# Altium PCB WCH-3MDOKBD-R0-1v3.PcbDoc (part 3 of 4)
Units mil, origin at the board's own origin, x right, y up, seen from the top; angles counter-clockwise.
Board outline 11710.74 x 4477.49 mil, 2 copper layers (Top Layer, Bottom Layer); 233 components, 145 nets, 545 pads, 1448 vias.
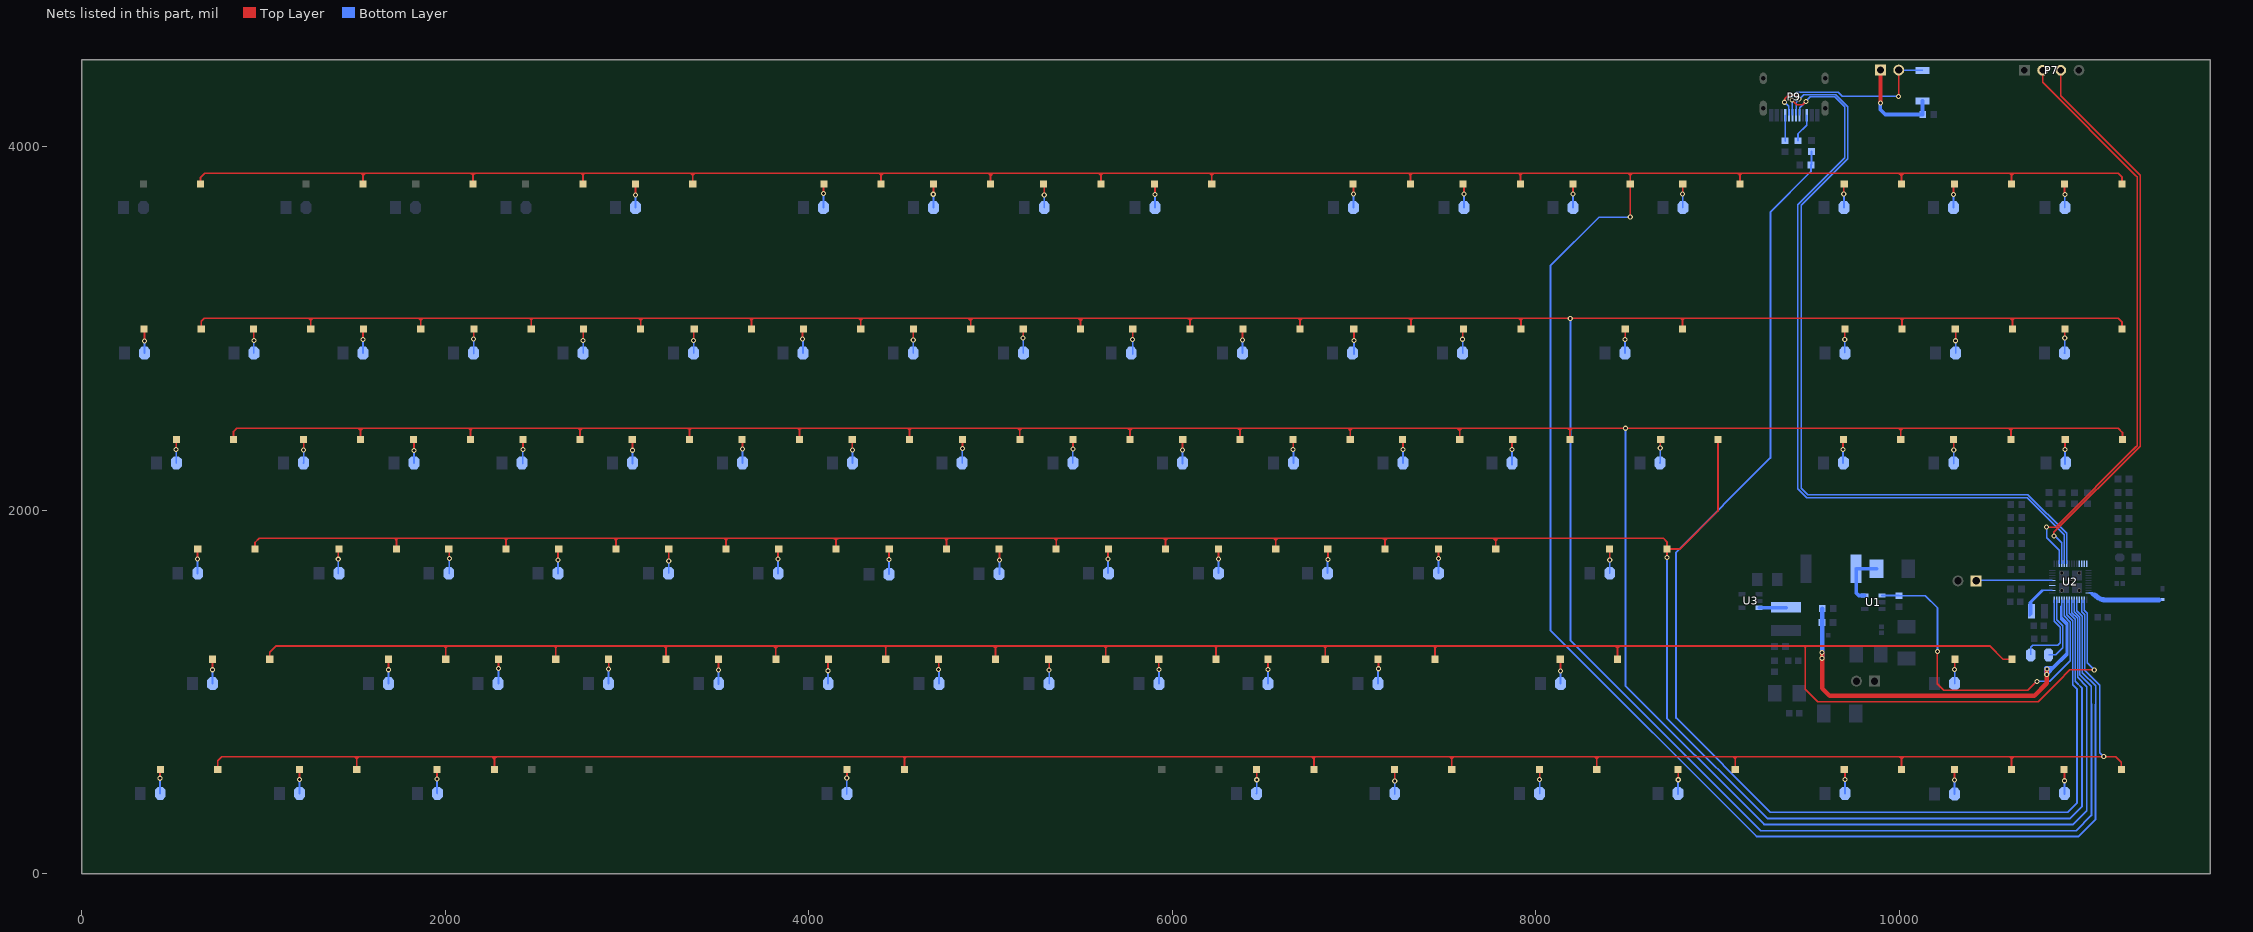
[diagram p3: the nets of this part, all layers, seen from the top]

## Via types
v1: diameter 28, hole 16, Top Layer to Bottom Layer, tented both sides, 1320 vias
v2: diameter 24, hole 12, Top Layer to Bottom Layer, tented both sides, 128 vias

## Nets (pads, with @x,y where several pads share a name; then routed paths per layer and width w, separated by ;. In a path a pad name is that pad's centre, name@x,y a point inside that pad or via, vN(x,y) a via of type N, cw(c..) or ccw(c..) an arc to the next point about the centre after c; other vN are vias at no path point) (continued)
NetD5_1: D5.1 S5.2 | length 134
  Top Layer w10: v1(3047.21,3732.37) 3047.38,3732.54 S5.2@3047.38,3793.8
  Bottom Layer w10: D5.1@3046.47,3664.15 v1@3046.47,3736.66
NetD6_1: D6.1 S6.2 | length 137.1
  Top Layer w10: v1(4081.34,3740.42) S6.2@4081.34,3798.84
  Bottom Layer w10: D6.1@4080.6,3664.02 v1@4080.6,3742.7
NetD7_1: D7.1 S7.2 | length 148
  Top Layer w10: v1(346.44,2930.45) S7.2@346.44,3005.08
  Bottom Layer w10: D7.1@346.44,2863.47 v1(346.44,2930.45) v1@346.44,2936.81
NetD8_1: D8.1 S8.2 | length 140.5
  Top Layer w10: v1(947.44,2931.58) S8.2@947.44,3003.99
  Bottom Layer w10: D8.1@947.44,2863.47 v1(947.44,2931.58)
NetD9_1: D9.1 S9.2 | length 141.4
  Top Layer w10: v1(1547.66,2938.16) S9.2@1547.66,3004.87
  Bottom Layer w10: D9.1@1547.66,2863.47 v1(1547.66,2938.16)
NetD10_1: D10.1 S10.2 | length 146
  Top Layer w10: v1(2157.01,2940.12) S10.2@2157.01,3005.49
  Bottom Layer w10: D10.1@2157.01,2859.47 v1(2157.01,2940.12)
NetD11_1: D11.1 S11.2 | length 142.9
  Top Layer w10: v1(2759.36,2933.25) S11.2@2759.36,3006.34
  Bottom Layer w10: D11.1@2759.36,2863.47 v1(2759.36,2933.25)
NetD12_1: D12.1 S12.2 | length 141.4
  Top Layer w10: v1(3367.08,2931.57) S12.2@3367.08,3004.9
  Bottom Layer w10: D12.1@3367.08,2863.47 3367.08,2869.62 v1(3367.08,2931.57)
NetD13_1: D13.1 S13.2 | length 144.2
  Top Layer w10: v1(520.39,2334.02) S13.2@520.39,2403.09
  Bottom Layer w10: v1(520.39,2334.02) 520.39,2259.88 D13.1@521.11,2259.16
NetD14_1: D14.1 S14.2 | length 141
  Top Layer w10: v1(1221.91,2329.7) S14.2@1221.91,2399.8
  Bottom Layer w10: D14.1@1221.16,2259.16 1221.91,2259.91 v1(1221.91,2329.7)
NetD15_1: D15.1 S15.2 | length 136.4
  Top Layer w10: v1(1828.18,2327.46) S15.2@1828.18,2395.54
  Bottom Layer w10: D15.1@1828.18,2259.16 v1(1828.18,2327.46)
NetD16_1: D16.1 S16.2 | length 144.5
  Top Layer w10: S16.2@2421.3,2396.47 2428.07,2389.7 v1(2428.07,2333.53)
  Bottom Layer w10: D16.1@2426.65,2256.21 2426.65,2333.53 v1(2428.07,2333.53)
NetD17_1: D17.1 S17.2 | length 132.6
  Top Layer w10: S17.2@3029.61,2388.74 3030.22,2388.14 v1(3030.22,2329.1)
  Bottom Layer w10: D17.1@3030.22,2256.38 v1(3030.22,2329.1)
NetD18_1: D18.1 S18.2 | length 136.8
  Top Layer w10: v1(3636.27,2335.52) S18.2@3636.27,2395.94
  Bottom Layer w10: D18.1@3636.27,2259.16 v1(3636.27,2335.52)
NetD19_1: D19.1 S19.2 | length 140.6
  Top Layer w10: v1(637.64,1731.27) S19.2@637.64,1791.23
  Bottom Layer w10: D19.1@637.64,1650.66 v1(637.64,1731.27)
NetD20_1: D20.1 S20.2 | length 140.2
  Top Layer w10: v1(1412.23,1729.57) S20.2@1412.23,1789.59
  Bottom Layer w10: D20.1@1412.23,1649.36 v1(1412.23,1729.57)
NetD21_1: D21.1 S21.2 | length 136.6
  Top Layer w10: S21.2@2020.09,1785.35 2022.85,1782.59 v1(2022.85,1732.52)
  Bottom Layer w10: D21.1@2022.85,1649.89 v1(2022.85,1732.52)
NetD22_1: D22.1 L1.2 U1.5 | length 297.9
  Bottom Layer w20: U1.5@9809.52,1530.18 9776.88,1530.18 9761.6,1545.46 L1.2@9761.6,1676.23 9762.43,1677.06 D22.1@9874.12,1677.06
NetD23_1: D23.1 S22.2 | length 139.2
  Top Layer w10: v1(2620.43,1725.84) S22.2@2620.43,1790.82
  Bottom Layer w10: D23.1@2620.43,1651.58 v1(2620.43,1725.84)
NetD25_1: D25.1 S23.2 | length 138.8
  Top Layer w10: v1(3230.17,1719.74) S23.2@3230.17,1791.5
  Bottom Layer w10: D25.1@3230.17,1652.68 v1(3230.17,1719.74)
NetD27_1: D27.1 S24.2 | length 141.8
  Top Layer w10: v1(3831.13,1729.93) S24.2@3831.13,1791.58
  Bottom Layer w10: D27.1@3831.13,1649.78 v1(3831.13,1729.93)
NetD28_1: D28.1 S25.2 | length 137.2
  Top Layer w10: v1(720.9,1121.62) S25.2@720.9,1182.43
  Bottom Layer w10: D28.1@720.9,1045.22 v1(720.9,1121.62)
NetD29_1: D29.1 S26.2 | length 133.9
  Top Layer w10: S26.2@1688.15,1178.83 1688.3,1178.68 v1(1688.3,1121.71)
  Bottom Layer w10: v1(1688.3,1121.71) 1688.3,1045.75 D29.1@1688.84,1045.22
NetD30_1: D30.1 S27.2 | length 134
  Top Layer w10: v1(2293.09,1129.34) 2293.09,1178.43 S27.2@2293.49,1178.83
  Bottom Layer w10: D30.1@2293.09,1045.02 v1(2293.09,1129.34)
NetD31_1: D31.1 S28.2 | length 146.8
  Top Layer w10: v1(2899.59,1125.29) S28.2@2899.59,1191.42
  Bottom Layer w10: D31.1@2898.24,1045.22 2898.24,1123.94 v1(2899.59,1125.29)
NetD32_1: D32.1 S29.2 | length 137.8
  Top Layer w10: v1(3503.65,1120.09) 3503.65,1178.34 S29.2@3504.14,1178.83
  Bottom Layer w10: D32.1@3503.65,1041.27 v1(3503.65,1120.09)
NetD33_1: D33.1 S30.2 | length 146.4
  Top Layer w10: v1(4106.44,1116.13) S30.2@4106.44,1191.23
  Bottom Layer w10: v1(4106.44,1116.13) 4106.44,1046.21 D33.1@4107.43,1045.22
NetD34_1: D34.1 S31.2 | length 132.3
  Top Layer w10: v1(430.8,524.84) S31.2@430.8,573.38
  Bottom Layer w10: D34.1@430.8,441.05 v1(430.8,524.84)
NetD35_1: D35.1 S32.2 | length 142.3
  Top Layer w10: v1(1198.31,517.48) S32.2@1198.31,583.2
  Bottom Layer w10: D35.1@1198.31,440.87 1198.31,449.18 v1(1198.31,517.48)
NetD36_1: D36.1 S33.2 | length 144.1
  Top Layer w10: v1(1955.94,519.52) S33.2@1955.94,584.5
  Bottom Layer w10: v1(1955.94,519.52) 1955.94,441.98 D36.1@1957.05,440.87
NetD37_1: D37.1 S34.2 | length 153.6
  Top Layer w10: v1@4211.04,518.17 S34.2@4211.04,573.38 S34.2@4211.04,584.2
  Bottom Layer w10: D37.1@4209.26,438.36 v1(4209.26,525.98)
NetD38_1: D38.1 S35.2 | length 132.9
  Top Layer w10: S35.2@6463.7,573.38 6464.36,572.72 v1(6464.36,516.16)
  Bottom Layer w10: D38.1@6464.02,440.87 6464.36,441.22 v1(6464.36,516.16)
NetD39_1: D39.1 S_Fn1.2 | length 141.3
  Top Layer w10: v1(7223.58,510.3) S_Fn1.2@7223.58,578.83
  Bottom Layer w10: D39.1@7223.58,437.53 D39.1@7223.58,440.87 v1(7223.58,510.3)
NetD40_1: D40.1 S36.2 | length 132.1
  Top Layer w10: v1(4685.16,3736.92) 4685.86,3737.61 S36.2@4685.86,3793.97
  Bottom Layer w10: D40.1@4686.32,3664.02 v1@4686.32,3738.79
NetD41_1: D41.1 S37.2 | length 140.5
  Top Layer w10: v1(5295.81,3733.02) S37.2@5295.81,3799.22
  Bottom Layer w10: D41.1@5295.81,3664.02 v1(5295.81,3733.02) v1@5295.81,3738.29
NetD42_1: D42.1 S38.2 | length 143.6
  Top Layer w10: v1(5905.07,3735.23) S38.2@5905.07,3803.59
  Bottom Layer w10: D42.1@5905.07,3664.02 v1(5905.07,3735.23) v1@5905.07,3739.32
NetD43_1: D43.1 S39.2 | length 139.5
  Top Layer w10: v1(6997.07,3739.18) S39.2@6997.07,3803.06
  Bottom Layer w10: D43.1@6995.94,3664.02 6995.94,3738.05 v1(6997.07,3739.18)
NetD44_1: D44.1 S40.2 | length 139.1
  Top Layer w10: v1(7604.2,3738.12) S40.2@7604.2,3803.15
  Bottom Layer w10: D44.1@7604.2,3664.02 v1(7604.2,3738.12)
NetD45_1: D45.1 S41.2 | length 136.4
  Top Layer w10: v1(8205.12,3739.5) S41.2@8205.12,3800.39
  Bottom Layer w10: v1(8205.12,3739.5) 8205.12,3664.13 D45.1@8205.22,3664.02
NetD46_1: D46.1 S42.2 | length 139.5
  Top Layer w10: v1(8807.11,3739.5) 8807.58,3739.98 S42.2@8807.58,3793.8 S42.2@8807.58,3801.76
  Bottom Layer w10: D46.1@8808.27,3664.02 v1@8808.27,3741.09
NetD47_1: D47.1 S43.2 | length 140.6
  Top Layer w10: v1(3966,2941.18) S43.2@3966,3003.17
  Bottom Layer w10: v1(3966,2941.18) 3968.09,2939.09 D47.1@3968.09,2863.47
NetD48_1: D48.1 S44.2 | length 141.1
  Top Layer w10: v1(4574.85,2936.23) S44.2@4574.85,3004.54
  Bottom Layer w10: D48.1@4574.85,2863.47 v1(4574.85,2936.23)
NetD49_1: D49.1 S45.2 | length 144.7
  Top Layer w10: v1(5179.6,2945.87) 5180.45,2946.72 S45.2@5180.45,2994.96 S45.2@5180.45,3007.45
  Bottom Layer w10: v1(5179.6,2945.87) 5180.47,2945 D49.1@5180.47,2863.47
NetD50_1: D50.1 S46.2 | length 137
  Top Layer w10: v1(5782.1,2937.09) S46.2@5782.1,2996.19
  Bottom Layer w10: D50.1@5782.1,2859.23 v1(5782.1,2937.09)
NetD51_1: D51.1 S47.2 | length 133.4
  Top Layer w10: v1(6386.92,2936.4) S47.2@6386.92,2996.88
  Bottom Layer w10: D51.1@6386.92,2863.47 v1(6386.92,2936.4)
NetD52_1: D52.1 S48.2 | length 150.3
  Top Layer w10: S48.2@6990.5,3003.78 6998.88,2995.4 v1(6998.88,2932.86)
  Bottom Layer w10: D52.1@6998.88,2856.99 v1(6998.88,2932.86)
NetD53_1: D53.1 S49.2 | length 138.5
  Top Layer w10: v1(7597.41,2939.64) S49.2@7597.41,3001.94
  Bottom Layer w10: D53.1@7597.3,2863.47 7597.41,2863.58 v1(7597.41,2939.64)
NetD54_1: D54.1 S50.2 | length 129.8
  Top Layer w10: S50.2@4239.53,2388.74 4239.53,2330.43 v1(4240.01,2329.95)
  Bottom Layer w10: D54.1@4239.96,2259.16 4240.01,2259.21 v1(4240.01,2329.95)
NetD55_1: D55.1 S51.2 | length 132.7
  Top Layer w10: v1(4845.53,2338.81) 4846.37,2339.65 S51.2@4846.37,2388.74
  Bottom Layer w10: D55.1@4844.14,2259.16 v1@4844.14,2341.61
NetD56_1: D56.1 S52.2 | length 132.1
  Top Layer w10: S52.2@5453.23,2388.74 5454.29,2387.68 v1(5454.29,2335.45)
  Bottom Layer w10: D56.1@5452.8,2259.16 v1@5452.8,2337.58
NetD57_1: D57.1 S53.2 | length 135.7
  Top Layer w10: v1(6055.6,2331.35) S53.2@6055.6,2389.95
  Bottom Layer w10: D57.1@6055.6,2254.23 D57.1@6055.6,2259.16 v1(6055.6,2331.35)
NetD58_1: D58.1 S54.2 | length 130.5
  Top Layer w10: S54.2@6664.28,2388.74 6664.94,2388.08 v1(6664.94,2332.01)
  Bottom Layer w10: v1(6664.94,2332.01) 6666.44,2330.51 D58.1@6666.44,2259.16
NetD59_1: D59.1 S55.2 | length 136.4
  Top Layer w10: v1(7269,2331.93) S55.2@7269,2395.49
  Bottom Layer w10: v1(7269,2331.93) 7269,2259.3 D59.1@7269.14,2259.16
NetD60_1: D60.1 S56.2 | length 146.5
  Top Layer w10: S56.2@7869.08,2390.27 v1(7869.08,2333.53) v1@7873.05,2337.49
  Bottom Layer w10: D60.1@7869.08,2249.4 D60.1@7869.08,2259.16 v1(7869.08,2333.53)
NetD61_1: D61.1 S57.2 | length 138.9
  Top Layer w10: v1(4442.36,1726.86) 4442.36,1784.96 S57.2@4442.76,1785.35
  Bottom Layer w10: D61.1@4442.3,1646.61 4442.3,1726.8 v1(4442.36,1726.86)
NetD62_1: D62.1 S58.2 | length 138.7
  Top Layer w10: S58.2@5046.27,1785.35 5048.62,1782.99 v1(5048.62,1725.98)
  Bottom Layer w10: D62.1@5048.62,1647.58 v1(5048.62,1725.98)
NetD63_1: D63.1 S59.2 | length 136.4
  Top Layer w10: v1(5646.28,1731) S59.2@5646.28,1789.39
  Bottom Layer w10: D63.1@5646.28,1653.01 v1(5646.28,1731)
NetD64_1: D64.1 S60.2 | length 133.9
  Top Layer w10: S60.2@6253.89,1785.35 6254.37,1784.87 v1(6254.37,1730.62)
  Bottom Layer w10: D64.1@6253.38,1652.04 6254.37,1653.03 v1(6254.37,1730.62)
NetD65_1: D65.1 S61.2 | length 141.2
  Top Layer w10: S61.2@6855.58,1785.35 6856.19,1784.74 v1(6856.19,1728.46)
  Bottom Layer w10: D65.1@6854.15,1651.91 v1@6854.15,1735.99
NetD66_1: D66.1 S62.2 | length 134.1
  Top Layer w10: S62.2@7464,1785.35 7464.51,1784.84 v1(7464.51,1732.79)
  Bottom Layer w10: D66.1@7463.53,1651.91 7464.51,1652.89 v1(7464.51,1732.79)
NetD67_1: D67.1 S63.2 | length 136.5
  Top Layer w10: v1(8684.1,2341.25) S63.2@8684.1,2394.85
  Bottom Layer w10: D67.1@8682.18,2259.16 8684.1,2261.08 v1(8684.1,2341.25)
NetD68_1: D68.1 S64.2 | length 149.4
  Top Layer w10: v1(4714.9,1122.33) S64.2@4714.9,1193.32
  Bottom Layer w10: D68.1@4717.14,1045.22 v1@4717.14,1123.66
NetD69_1: D69.1 S65.2 | length 133.6
  Top Layer w10: v1(5322.73,1120.41) S65.2@5322.73,1178.83
  Bottom Layer w10: D69.1@5322.73,1045.22 v1(5322.73,1120.41)
NetD70_1: D70.1 S66.2 | length 134.1
  Top Layer w10: S66.2@5925.44,1178.83 5925.44,1124.13 v1(5926.55,1123.02)
  Bottom Layer w10: D70.1@5926.55,1045.22 v1(5926.55,1123.02)
NetD71_1: D71.1 S67.2 | length 133.9
  Top Layer w10: v1(6526.43,1122.05) S67.2@6526.44,1178.83
  Bottom Layer w10: D71.1@6525.65,1045.22 6526.43,1046 v1(6526.43,1122.05)
NetD72_1: D72.1 S68.2 | length 145.1
  Top Layer w10: v1(7133.51,1126.77) S68.2@7133.51,1187.91
  Bottom Layer w10: D72.1@7131.13,1045.22 v1@7131.13,1129.15
NetD73_1: D73.1 S69.2 | length 142.6
  Top Layer w10: v1(8136.22,1113.6) S69.2@8136.22,1187.79
  Bottom Layer w10: D73.1@8136.22,1045.22 v1(8136.22,1113.6)
NetD74_1: D74.1 S71.2 | length 143.2
  Top Layer w10: v1(8020.91,518.8) S71.2@8020.91,584.11
  Bottom Layer w10: D74.1@8020.91,440.87 v1(8020.91,518.8)
NetD75_1: D75.1 S72.2 | length 144.5
  Top Layer w10: v1(8783.06,516.6) S72.2@8783.06,580.01
  Bottom Layer w10: D75.1@8781.21,437.72 D75.1@8781.21,440.87 v1@8781.21,518.79
NetD76_1: D76.1 S73.2 | length 141.6
  Top Layer w10: v1@9693.64,3735.52 v1(9693.64,3738.1) S73.2@9693.64,3802.03
  Bottom Layer w10: D76.1@9694.83,3664.02 v1@9694.83,3739.15
NetD77_1: D77.1 S74.2 | length 143
  Top Layer w10: v1(10297.44,3736.7) S74.2@10297.44,3802.98
  Bottom Layer w10: D77.1@10297.44,3664.02 v1(10297.44,3736.7) v1@10297.44,3740.8
NetD78_1: D78.1 S75.2 | length 130.2
  Top Layer w10: S75.2@10908.61,3793.8 10908.61,3737.64 v1(10909.68,3736.57)
  Bottom Layer w10: D78.1@10909.68,3664.02 v1(10909.68,3736.57)
NetD79_1: D79.1 S76.2 | length 142.5
  Top Layer w10: v1(8490.15,2938.78) 8490.46,2938.78 8491.69,2940.01 S76.2@8491.69,2994.96 S76.2@8491.69,3005.15
  Bottom Layer w10: D79.1@8490.15,2863.47 v1(8490.15,2938.78)
NetD80_1: D80.1 S77.2 | length 134.6
  Top Layer w10: v1(9699.13,2938.04) S77.2@9699.13,2999.35
  Bottom Layer w10: D80.1@9699.13,2864.77 v1(9699.13,2938.04)
NetD81_1: D81.1 S78.2 | length 139.1
  Top Layer w10: v1(10309.39,2931.52) S78.2@10309.39,3002.6
  Bottom Layer w10: D81.1@10309.39,2863.47 v1(10309.39,2931.52)
NetD82_1: D82.1 S79.2 | length 132
  Top Layer w10: v1(10909.21,2945.36) 10909.21,2994.21 S79.2@10909.97,2994.96
  Bottom Layer w10: D82.1@10908.74,2863.47 10909.21,2863.94 v1(10909.21,2945.36)
NetD83_1: D83.1 S80.2 | length 137.3
  Top Layer w10: v1(9688.8,2332.41) S80.2@9688.8,2395.19
  Bottom Layer w10: D83.1@9688.8,2257.89 v1(9688.8,2332.41)
NetD84_1: D84.1 S81.2 | length 131.5
  Top Layer w10: v1(10298.64,2329.83) S81.2@10298.64,2386.67
  Bottom Layer w10: D84.1@10298.64,2255.15 D84.1@10298.64,2259.16 v1(10298.64,2329.83)
NetD85_1: D85.1 S82.2 | length 138.7
  Top Layer w10: v1(10911.34,2332.49) S82.2@10911.34,2392.87
  Bottom Layer w10: D85.1@10911.34,2254.14 v1(10911.34,2332.49)
NetD86_1: D86.1 S83.2 | length 133.7
  Top Layer w10: S83.2@8405.85,1785.35 8406.18,1785.02 v1(8406.18,1726.29)
  Bottom Layer w10: v1(8406.18,1726.29) 8406.18,1652.29 D86.1@8406.56,1651.91
NetD87_1: D87.1 S84.2 | length 136.5
  Top Layer w10: v1(10303.89,1122.05) S84.2@10303.89,1181.77
  Bottom Layer w10: D87.1@10303.89,1045.22 v1(10303.89,1122.05)
NetD88_1: D88.1 S85.2 | length 143.9
  Top Layer w10: v1(9700.87,518.17) S85.2@9700.87,584.79
  Bottom Layer w10: D88.1@9700.87,440.87 v1(9700.87,518.17)
NetD89_1: D89.1 S86.2 | length 147.9
  Top Layer w10: v1(10303.66,514.46) S86.2@10303.66,585.44
  Bottom Layer w10: D89.1@10303.66,437.55 v1(10303.66,514.46)
NetD90_1: D90.1 S87.2 | length 148
  Top Layer w10: v1(10907.66,511.07) S87.2@10907.66,581.35
  Bottom Layer w10: D90.1@10908.26,437.41 D90.1@10908.26,441.09 v1@10908.26,515.16
NetE1_1: E1.1 U2.34 | length 564.8
  Bottom Layer w7: 11075.28,1527.52 11070.76,1532.04 ccw(c11042.5,1503.78) U2.34@11042.5,1543.75 ; 11077.67,1516.72 11056.4,1537.99 ccw(c11042.5,1524.09) U2.34@11042.5,1543.75 ; 11083.07,1526.21 11081.81,1527.47 ccw(c11042.5,1488.16) U2.34@11042.5,1543.75 ; 11083.9,1530.76 ccw(c11052.55,1499.41) U2.34@11052.55,1543.75 ; 11091.68,1532.51 ccw(c11064.53,1505.36) 11064.53,1543.75 U2.34@11052.55,1543.75 ; U2.34@11042.5,1543.75 U2.34@11052.55,1543.75
  Bottom Layer w28.1: 11083.07,1526.21 ccw(c11131.36,1574.5) 11131.36,1506.2 11426.79,1506.2
NetL2_1: L2.1 U2.2 | length 645.3
  Bottom Layer w7: 10794.37,1557.49 10791.14,1557.49 ; U2.2@10841.57,1557.49 10791.14,1557.49 ; L2.1@10714.85,1426.41 L2.1@10714.85,1439.54 ; L2.1@10714.85,1426.41 10714.85,1416.98 L2.1@10722.52,1424.64 ; L2.1@10714.85,1426.41 L2.1@10722.52,1434.08 ; L2.1@10714.85,1439.54 10720.31,1434.08 L2.1@10722.52,1434.08 ; L2.1@10714.85,1439.54 L2.1@10714.85,1454.87 ; L2.1@10714.85,1439.54 L2.1@10722.52,1447.21 ; L2.1@10714.85,1454.87 L2.1@10722.52,1462.54 ; L2.1@10714.85,1454.87 L2.1@10714.85,1469.13 ; L2.1@10714.85,1454.87 L2.1@10722.52,1447.21 ; L2.1@10714.85,1469.13 L2.1@10714.85,1477.97 ; L2.1@10714.85,1469.13 L2.1@10722.52,1469.13 ; L2.1@10714.85,1469.13 10721.44,1462.54 L2.1@10722.52,1462.54 ; L2.1@10714.85,1477.97 10719.29,1477.97 L2.1@10722.52,1481.2 ; L2.1@10714.85,1477.97 L2.1@10722.52,1470.3 ; L2.1@10714.85,1477.97 10714.85,1488.87 ; 10714.85,1488.87 L2.1@10722.52,1481.2 ; 10714.85,1488.87 10722.52,1488.87 ; 10714.85,1488.87 10783.47,1557.49 10791.14,1557.49 ; L2.1@10722.52,1424.64 L2.1@10722.52,1434.08 ; L2.1@10722.52,1424.64 10728.64,1430.77 L2.1@10728.64,1445.57 ; L2.1@10722.52,1434.08 L2.1@10722.52,1447.21 ; L2.1@10722.52,1447.21 L2.1@10722.52,1462.54 ; L2.1@10722.52,1447.21 L2.1@10726.4,1443.33 ; L2.1@10722.52,1462.54 L2.1@10722.52,1469.13 ; L2.1@10722.52,1462.54 L2.1@10726.4,1466.42 ; L2.1@10722.52,1469.13 L2.1@10722.52,1470.3 ; L2.1@10722.52,1469.13 L2.1@10723.68,1469.13 ; L2.1@10722.52,1470.3 L2.1@10722.52,1481.2 ; L2.1@10722.52,1470.3 L2.1@10723.68,1469.13 ; L2.1@10722.52,1481.2 10722.52,1488.87 ; L2.1@10722.52,1481.2 10726.4,1477.32 L2.1@10726.4,1466.42 ; 10722.52,1488.87 10728.64,1494.99 ; L2.1@10723.68,1469.13 L2.1@10726.4,1466.42 ; L2.1@10726.4,1443.33 L2.1@10726.4,1466.42 ; L2.1@10726.4,1443.33 L2.1@10728.64,1445.57 ; L2.1@10728.64,1445.57 10728.64,1494.99 ; 10728.64,1494.99 10791.14,1557.49
NetL4_1: L4.1 U3.3 | length 148.2
  Bottom Layer w20: U3.3@9228.06,1462.52 L4.1@9376.23,1462.52
NetP6_1: P6.1 R300.1 S70.1 | length 540.4
  Top Layer w20: v1@9896.11,4240.06 P6.1@9896.11,4420.24
  Bottom Layer w20: v1@9894.17,4241.92 9894.17,4203.59 9922.1,4175.66 R300.1@10128.51,4175.66 10127.09,4177.09 S70.1@10127.09,4251.02
  other v1: 9894.77,4240.06
NetP9_A5: P9.A5 R10.1 | length 142.6
  Bottom Layer w10: R10.1@9372.01,4029.54 P9.A5@9372.01,4172.15
NetP9_B5: P9.B5 R11.1 | length 159.7
  Bottom Layer w10: R11.1@9442.13,4032.34 9442.13,4068.95 9490.12,4116.94 P9.B5@9490.12,4172.15
PA0: S1.1 S2.1 S3.1 S4.1 S5.1 S6.1 S36.1 S37.1 S38.1 S39.1 S40.1 S41.1 S42.1 S73.1 S74.1 S75.1 U2.39 | length 19418.2
  Top Layer w10: S1.1@654.86,3793.8 654.86,3829.59 677.54,3852.28 1539.27,3852.28 ; S2.1@1548.73,3793.8 1548.73,3841.66 ; S3.1@2153.27,3793.8 2153.27,3841.02 ; S4.1@2757.8,3793.8 2757.8,3843.06 ; S5.1@3362.34,3793.8 3362.34,3840.86 ; S6.1@4398.26,3793.97 4398.26,3841.44 ; S36.1@5000.82,3793.97 5000.82,3839.61 ; S37.1@5607.27,3794.25 5607.27,3840.64 ; S38.1@6216.74,3794.24 6216.74,3841.77 ; S39.1@7309.83,3793.8 7309.83,3841.63 ; S40.1@7914.98,3793.8 7914.98,3841.77 ; v1@8519.58,3610.39 S41.1@8519.58,3793.88 8519.58,3841.76 ; S42.1@9122.54,3793.8 9122.54,3841.12 ; S73.1@10011.03,3793.8 10011.03,3839.1 ; S74.1@10617.3,3793.8 10617.3,3841.41 ; S75.1@11223.57,3793.8 11223.57,3832.75 11204.04,3852.28 10628.16,3852.28 ; 1539.27,3852.28 1550.27,3852.28 ; 1539.27,3852.28 1539.27,3851.12 1548.73,3841.66 ; 1548.73,3841.66 1559.35,3852.28 ; 1548.73,3841.66 1548.73,3850.74 1550.27,3852.28 ; 1550.27,3852.28 1559.35,3852.28 ; 1559.35,3852.28 2142.01,3852.28 ; 2142.01,3852.28 2154.24,3852.28 ; 2142.01,3852.28 2153.27,3841.02 ; 2153.27,3841.02 2164.52,3852.28 ; 2153.27,3841.02 2153.27,3851.31 2154.24,3852.28 ; 2154.24,3852.28 2164.52,3852.28 ; 2164.52,3852.28 2748.58,3852.28 ; 2748.58,3852.28 2758.87,3852.28 ; 2748.58,3852.28 2757.8,3843.06 ; 2757.8,3843.06 2767.02,3852.28 ; 2757.8,3843.06 2757.8,3851.21 2758.87,3852.28 ; 2758.87,3852.28 2767.02,3852.28 ; 2767.02,3852.28 3351.11,3852.28 ; 3351.11,3852.28 3360.58,3852.28 ; 3351.11,3852.28 3351.11,3852.08 3362.34,3840.86 ; 3360.58,3852.28 3373.76,3852.28 ; 3360.58,3852.28 3362.34,3850.52 3362.34,3840.86 ; 3362.34,3840.86 3373.76,3852.28 ; 3373.76,3852.28 4387.42,3852.28 ; 4387.42,3852.28 4397.66,3852.28 ; 4387.42,3852.28 4398.26,3841.44 ; 4397.66,3852.28 4409.1,3852.28 ; 4397.66,3852.28 4398.26,3851.67 4398.26,3841.44 ; 4398.26,3841.44 4409.1,3852.28 ; 4409.1,3852.28 4989.28,3852.28 ; 4989.28,3852.28 5003.72,3852.28 ; 4989.28,3852.28 4989.28,3851.15 5000.82,3839.61 ; 5000.82,3839.61 5013.48,3852.28 ; 5000.82,3839.61 5000.82,3849.37 5003.72,3852.28 ; 5003.72,3852.28 5013.48,3852.28 ; 5013.48,3852.28 5595.63,3852.28 ; 5595.63,3852.28 5605.54,3852.28 ; 5595.63,3852.28 5607.27,3840.64 ; 5605.54,3852.28 5617.82,3852.28 ; 5605.54,3852.28 5607.27,3850.55 5607.27,3841.72 ; 5607.27,3840.64 5607.27,3841.72 ; 5607.27,3841.72 5617.82,3852.28 ; 5617.82,3852.28 6206.23,3852.28 ; 6206.23,3852.28 6219.21,3852.28 ; 6206.23,3852.28 6216.74,3841.77 ; 6216.74,3841.77 6227.25,3852.28 ; 6216.74,3841.77 6216.74,3849.81 6219.21,3852.28 ; 6219.21,3852.28 6227.25,3852.28 ; 6227.25,3852.28 7299.19,3852.28 ; 7299.19,3852.28 7308.57,3852.28 ; 7299.19,3852.28 7309.83,3841.63 ; 7308.57,3852.28 7320.48,3852.28 ; 7308.57,3852.28 7309.83,3851.02 7309.83,3841.63 ; 7309.83,3841.63 7320.48,3852.28 ; 7320.48,3852.28 7904.48,3852.28 ; 7904.48,3852.28 7914.06,3852.28 ; 7904.48,3852.28 7914.98,3841.77 ; 7914.06,3852.28 7925.48,3852.28 ; 7914.06,3852.28 7914.98,3851.36 7914.98,3841.77 ; 7914.98,3841.77 7925.48,3852.28 ; 7925.48,3852.28 8509.06,3852.28 ; 8509.06,3852.28 8521.05,3852.28 ; 8509.06,3852.28 8519.58,3841.76 ; 8519.58,3841.76 8530.09,3852.28 ; 8519.58,3841.76 8519.58,3850.8 8521.05,3852.28 ; 8521.05,3852.28 8530.09,3852.28 ; 8530.09,3852.28 9112.41,3852.28 ; 9112.41,3852.28 9123.14,3852.28 ; 9112.41,3852.28 9112.41,3851.25 9122.54,3841.12 ; 9122.54,3841.12 9133.7,3852.28 ; 9122.54,3841.12 9122.54,3851.68 9123.14,3852.28 ; 9123.14,3852.28 9133.7,3852.28 ; 9133.7,3852.28 10000.77,3852.28 ; 10000.77,3852.28 10012.2,3852.28 ; 10000.77,3852.28 10000.77,3849.35 10011.03,3839.1 ; 10011.03,3839.1 10011.03,3839.54 ; 10011.03,3839.54 10011.03,3851.11 10012.2,3852.28 ; 10011.03,3839.54 10023.77,3852.28 ; 10012.2,3852.28 10023.77,3852.28 ; 10023.77,3852.28 10606.44,3852.28 ; 10606.44,3852.28 10615.06,3852.28 ; 10606.44,3852.28 10617.3,3841.41 ; 10615.06,3852.28 10628.16,3852.28 ; 10615.06,3852.28 10617.3,3850.04 10617.3,3841.41 ; 10617.3,3841.41 10628.16,3852.28
  Bottom Layer w7: U2.39@10975.43,1506.72 10975.43,1445.44 11005.99,1414.88 11005.99,1105.57 11079.24,1032.32 11079.24,929.84
  Bottom Layer w10: v1@8519.58,3610.37 8347.13,3610.37 8079.63,3342.86 8079.63,1339.01 9213.58,205.05 10986.29,205.05 11079.24,297.99 11079.24,929.84
  other v1: 8519,3611.99
PA1: S7.1 S8.1 S9.1 S10.1 S11.1 S12.1 S43.1 S44.1 S45.1 S46.1 S47.1 S48.1 S49.1 S76.1 S77.1 S78.1 S79.1 U2.40 | length 18367.1
  Top Layer w10: S7.1@658.49,2994.96 658.49,3037.98 675.4,3054.89 1248.97,3054.89 ; S8.1@1260.41,2994.96 1260.41,3043.45 ; S9.1@1866.19,2994.96 1866.19,3044.35 ; S10.1@2473.99,2994.96 2473.99,3045.8 ; S11.1@3075.53,2994.96 3075.53,3043.76 ; S12.1@3685.01,2994.96 3685.01,3044.18 ; S43.1@4286.55,2994.96 4286.55,3044.31 ; S44.1@4890.96,2994.96 4890.96,3041.8 ; S45.1@5495.41,2994.96 5495.41,3042.24 ; S46.1@6097.77,2994.96 6097.77,3043.29 ; S47.1@6703.15,2994.96 6703.15,3043.66 ; S48.1@7312.97,2994.96 7312.97,3043.68 ; S49.1@7917.42,2994.96 7917.42,3044.05 ; S76.1@8806.65,2994.96 8806.65,3043.76 ; S77.1@10014.84,2994.96 10014.84,3043.77 ; S78.1@10621.68,2994.96 10621.68,3043.67 ; S79.1@11224.93,2994.96 11224.93,3033.21 11203.25,3054.89 10632.9,3054.89 ; 1248.97,3054.89 1261.07,3054.89 ; 1248.97,3054.89 1260.41,3043.45 ; 1260.41,3043.45 1271.86,3054.89 ; 1260.41,3043.45 1260.41,3054.23 1261.07,3054.89 ; 1261.07,3054.89 1271.86,3054.89 ; 1271.86,3054.89 1855.65,3054.89 ; 1855.65,3054.89 1866.09,3054.89 ; 1855.65,3054.89 1866.19,3044.35 ; 1866.09,3054.89 1876.74,3054.89 ; 1866.09,3054.89 1866.19,3054.79 1866.19,3044.35 ; 1866.19,3044.35 1876.74,3054.89 ; 1876.74,3054.89 2464.89,3054.89 ; 2464.89,3054.89 2472.86,3054.89 ; 2464.89,3054.89 2473.99,3045.8 ; 2472.86,3054.89 2483.08,3054.89 ; 2472.86,3054.89 2473.99,3053.77 2473.99,3045.8 ; 2473.99,3045.8 2483.08,3054.89 ; 2483.08,3054.89 3064.4,3054.89 ; 3064.4,3054.89 3074.7,3054.89 ; 3064.4,3054.89 3075.53,3043.76 ; 3074.7,3054.89 3086.66,3054.89 ; 3074.7,3054.89 3075.53,3054.07 3075.53,3043.76 ; 3075.53,3043.76 3086.66,3054.89 ; 3086.66,3054.89 3674.29,3054.89 ; 3674.29,3054.89 3685.13,3054.89 ; 3674.29,3054.89 3685.01,3044.18 ; 3685.01,3044.18 3695.72,3054.89 ; 3685.01,3044.18 3685.01,3054.77 3685.13,3054.89 ; 3685.13,3054.89 3695.72,3054.89 ; 3695.72,3054.89 4275.97,3054.89 ; 4275.97,3054.89 4287.94,3054.89 ; 4275.97,3054.89 4286.55,3044.31 ; 4286.55,3044.31 4297.14,3054.89 ; 4286.55,3044.31 4286.55,3053.51 4287.94,3054.89 ; 4287.94,3054.89 4297.14,3054.89 ; 4297.14,3054.89 4877.87,3054.89 ; 4877.87,3054.89 4888.77,3054.89 ; 4877.87,3054.89 4890.96,3041.8 ; 4888.77,3054.89 4902.18,3054.89 ; 4888.77,3054.89 4890.96,3052.7 4890.96,3043.68 ; 4890.96,3041.8 4890.96,3043.68 ; 4890.96,3043.68 4902.18,3054.89 ; 4902.18,3054.89 5482.76,3054.89 ; 5482.76,3054.89 5493.4,3054.89 ; 5482.76,3054.89 5495.41,3042.24 ; 5493.4,3054.89 5508.06,3054.89 ; 5493.4,3054.89 5495.41,3052.88 5495.41,3042.24 ; 5495.41,3042.24 5508.06,3054.89 ; 5508.06,3054.89 6086.17,3054.89 ; 6086.17,3054.89 6098.42,3054.89 ; 6086.17,3054.89 6097.77,3043.29 ; 6097.77,3043.29 6109.38,3054.89 ; 6097.77,3043.29 6097.77,3054.24 6098.42,3054.89 ; 6098.42,3054.89 6109.38,3054.89 ; 6109.38,3054.89 6691.92,3054.89 ; 6691.92,3054.89 6702.66,3054.89 ; 6691.92,3054.89 6703.15,3043.66 ; 6702.66,3054.89 6714.38,3054.89 ; 6702.66,3054.89 6703.15,3054.4 6703.15,3043.66 ; 6703.15,3043.66 6714.38,3054.89 ; 6714.38,3054.89 7301.75,3054.89 ; 7301.75,3054.89 7314.46,3054.89 ; 7301.75,3054.89 7312.97,3043.68 ; 7312.97,3043.68 7324.18,3054.89 ; 7312.97,3043.68 7312.97,3053.4 7314.46,3054.89 ; 7314.46,3054.89 7324.18,3054.89 ; 7324.18,3054.89 7906.57,3054.89 ; 7906.57,3054.89 7915.55,3054.89 ; 7906.57,3054.89 7917.42,3044.05 ; 7915.55,3054.89 7928.27,3054.89 ; 7915.55,3054.89 7917.42,3053.02 7917.42,3044.05 ; 7917.42,3044.05 7928.27,3054.89 ; 7928.27,3054.89 8795.51,3054.89 ; 8795.51,3054.89 8808.68,3054.89 ; 8795.51,3054.89 8806.65,3043.76 ; 8806.65,3043.76 8806.65,3044.01 ; 8806.65,3044.01 8806.65,3052.86 8808.68,3054.89 ; 8806.65,3044.01 8817.53,3054.89 ; 8808.68,3054.89 8817.53,3054.89 ; 8817.53,3054.89 10004.66,3054.89 ; 10004.66,3054.89 10013.43,3054.89 ; 10004.66,3054.89 10004.66,3053.94 10014.84,3043.77 ; 10013.43,3054.89 10023.83,3054.89 ; 10013.43,3054.89 10014.84,3053.49 10014.84,3045.9 ; 10014.84,3043.77 10014.84,3045.9 ; 10014.84,3045.9 10023.83,3054.89 ; 10023.83,3054.89 10610.45,3054.89 ; 10610.45,3054.89 10619.31,3054.89 ; 10610.45,3054.89 10621.68,3043.67 ; 10619.31,3054.89 10632.9,3054.89 ; 10619.31,3054.89 10621.68,3052.52 10621.68,3043.67 ; 10621.68,3043.67 10632.9,3054.89
  Bottom Layer w7: U2.40@10961.65,1506.72 10961.65,1440.84 10992.99,1409.5 10992.99,1093.81 11055.73,1031.07 11055.73,933.26
  Bottom Layer w10: v1@8189.85,3053.03 8189.85,1284.46 9238.03,236.28 10971.82,236.28 11055.73,320.19 11055.73,933.26
  other v1: 8189.08,3053.03
PA2: S13.1 S14.1 S15.1 S16.1 S17.1 S18.1 S50.1 S51.1 S52.1 S53.1 S54.1 S55.1 S56.1 S80.1 S81.1 S82.1 U2.41 | length 17285
  Top Layer w10: S13.1@836.42,2388.74 836.42,2432.02 854.25,2449.86 1522.14,2449.86 ; S14.1@1535.07,2388.74 1535.07,2436.93 ; S15.1@2140.31,2388.74 2140.31,2439.5 ; S16.1@2742.63,2388.74 2742.63,2438.94 ; S17.1@3344.57,2388.74 3344.57,2440.48 ; S18.1@3948.78,2388.74 3948.78,2440.32 ; S50.1@4554.49,2388.74 4554.49,2439.79 ; S51.1@5161.33,2388.74 5161.33,2439.86 ; S52.1@5768.19,2388.74 5768.19,2437.6 ; S53.1@6372.38,2388.74 6372.38,2437.85 ; S54.1@6979.24,2388.74 6979.24,2437 ; S55.1@7581.17,2388.74 7581.17,2435.57 ; S56.1@8188.01,2388.74 8188.01,2438.48 ; S80.1@10007.05,2388.74 10007.05,2439.12 ; S81.1@10612.8,2388.74 10612.8,2438.7 ; S82.1@11226.87,2388.74 11226.87,2425.91 11202.93,2449.86 10622.92,2449.86 ; 1522.14,2449.86 1534.65,2449.86 ; 1522.14,2449.86 1535.07,2436.93 ; 1534.65,2449.86 1545.84,2449.86 ; 1534.65,2449.86 1535.07,2449.44 1535.07,2439.08 ; 1535.07,2436.93 1535.07,2439.08 ; 1535.07,2439.08 1545.84,2449.86 ; 1545.84,2449.86 2129.95,2449.86 ; 2129.95,2449.86 2142.83,2449.86 ; 2129.95,2449.86 2140.31,2439.5 ; 2140.31,2439.5 2150.67,2449.86 ; 2140.31,2439.5 2140.31,2447.34 2142.83,2449.86 ; 2142.83,2449.86 2150.67,2449.86 ; 2150.67,2449.86 2731.72,2449.86 ; 2731.72,2449.86 2742.08,2449.86 ; 2731.72,2449.86 2742.63,2438.94 ; 2742.08,2449.86 2753.55,2449.86 ; 2742.08,2449.86 2742.63,2449.31 2742.63,2438.94 ; 2742.63,2438.94 2753.55,2449.86 ; 2753.55,2449.86 3335.2,2449.86 ; 3335.2,2449.86 3343.93,2449.86 ; 3335.2,2449.86 3344.57,2440.48 ; 3343.93,2449.86 3353.95,2449.86 ; 3343.93,2449.86 3344.57,2449.21 3344.57,2440.48 ; 3344.57,2440.48 3353.95,2449.86 ; 3353.95,2449.86 3939.23,2449.86 ; 3939.23,2449.86 3949.8,2449.86 ; 3939.23,2449.86 3948.78,2440.32 ; 3948.78,2440.32 3958.32,2449.86 ; 3948.78,2440.32 3948.78,2448.84 3949.8,2449.86 ; 3949.8,2449.86 3958.32,2449.86 ; 3958.32,2449.86 4544.42,2449.86 ; 4544.42,2449.86 4553.04,2449.86 ; 4544.42,2449.86 4554.49,2439.79 ; 4553.04,2449.86 4564.55,2449.86 ; 4553.04,2449.86 4554.49,2448.41 4554.49,2439.79 ; 4554.49,2439.79 4564.55,2449.86 ; 4564.55,2449.86 5153.23,2449.86 ; 5153.23,2449.86 5161.25,2449.86 ; 5153.23,2449.86 5153.23,2447.95 5161.33,2439.86 ; 5161.25,2449.86 5171.33,2449.86 ; 5161.25,2449.86 5161.33,2449.77 5161.33,2439.86 ; 5161.33,2439.86 5171.33,2449.86 ; 5171.33,2449.86 5757.53,2449.86 ; 5757.53,2449.86 5766.98,2449.86 ; 5757.53,2449.86 5757.53,2448.26 5768.19,2437.6 ; 5766.98,2449.86 5780.45,2449.86 ; 5766.98,2449.86 5768.19,2448.65 5768.19,2437.6 ; 5768.19,2437.6 5780.45,2449.86 ; 5780.45,2449.86 6362.33,2449.86 ; 6362.33,2449.86 6371.49,2449.86 ; 6362.33,2449.86 6362.33,2447.91 6372.38,2437.85 ; 6371.49,2449.86 6383.17,2449.86 ; 6371.49,2449.86 6372.38,2448.96 6372.38,2439.07 ; 6372.38,2437.85 6372.38,2439.07 ; 6372.38,2439.07 6383.17,2449.86 ; 6383.17,2449.86 6966.38,2449.86 ; 6966.38,2449.86 6978.89,2449.86 ; 6966.38,2449.86 6979.24,2437 ; 6978.89,2449.86 6990.3,2449.86 ; 6978.89,2449.86 6979.24,2449.51 6979.24,2438.79 ; 6979.24,2437 6979.24,2438.79 ; 6979.24,2438.79 6990.3,2449.86 ; 6990.3,2449.86 7566.89,2449.86 ; 7566.89,2449.86 7580.39,2449.86 ; 7566.89,2449.86 7581.17,2435.57 ; 7580.39,2449.86 7593.25,2449.86 ; 7580.39,2449.86 7581.17,2449.08 7581.17,2437.77 ; 7581.17,2435.57 7581.17,2437.77 ; 7581.17,2437.77 7593.25,2449.86 ; 7593.25,2449.86 8178.82,2449.86 ; 8178.82,2449.86 8189.25,2449.86 ; 8178.82,2449.86 8178.82,2447.67 8188.01,2438.48 ; 8188.01,2438.48 8189.47,2438.48 8200.85,2449.86 ; 8188.01,2438.48 8188.01,2448.62 8189.25,2449.86 ; 8189.25,2449.86 8200.85,2449.86 ; 8200.85,2449.86 9996.32,2449.86 ; 9996.32,2449.86 10006.93,2449.86 ; 9996.32,2449.86 10007.05,2439.12 ; 10006.93,2449.86 10017.78,2449.86 ; 10006.93,2449.86 10007.05,2449.74 10007.05,2439.12 ; 10007.05,2439.12 10017.78,2449.86 ; 10017.78,2449.86 10601.64,2449.86 ; 10601.64,2449.86 10612.82,2449.86 ; 10601.64,2449.86 10612.8,2438.7 ; 10612.8,2438.7 10622.92,2448.81 10622.92,2449.86 ; 10612.8,2438.7 10612.8,2449.84 ; 10612.82,2449.86 10622.92,2449.86
  Bottom Layer w7: U2.41@10947.87,1506.72 10947.87,1436.23 10979.52,1404.58 10979.52,1080.29 11030.51,1029.3 11030.51,1006.31
  Bottom Layer w10: v1@8492.68,2455.64 8492.68,2450.17 8492.68,1033.42 9255.57,270.53 10955.49,270.53 11030.51,345.54 11030.51,1006.31
  other v1: 8492.42,2450.17
PA3: S19.1 S20.1 S21.1 S22.1 S23.1 S24.1 S57.1 S58.1 S59.1 S60.1 S61.1 S62.1 S63.1 S83.1 U2.42 | length 14251.2
  Top Layer w10: S19.1@953.93,1785.35 953.93,1821.64 976.86,1844.56 1721.65,1844.56 ; S20.1@1731.56,1785.35 1731.56,1834.65 1721.65,1844.56 ; S21.1@2335.05,1785.35 2335.05,1835.06 ; S22.1@2939.64,1785.35 2939.64,1833.7 ; S23.1@3545.39,1785.35 3545.39,1834.65 ; S24.1@4150.01,1785.35 4150.01,1833.19 ; S57.1@4757.72,1785.35 4757.72,1834.15 ; S58.1@5361.23,1785.35 5361.23,1834.99 ; S59.1@5963.21,1785.35 5963.21,1832.28 ; S60.1@6568.85,1785.35 6568.85,1834.11 ; S61.1@7170.54,1785.35 7170.54,1832.68 ; S62.1@7778.96,1785.35 7778.96,1831.94 ; v1(8720.81,1739.65) S83.1@8720.81,1785.35 ; S83.1@8722.7,1783.46 S83.1@8720.81,1785.35 ; S63.1@9001.52,2388.74 9001.52,1994.69 8792.19,1785.35 S83.1@8720.81,1785.35 ; 1721.65,1844.56 1730.74,1844.56 ; 1730.74,1844.56 1740.55,1844.56 ; 1730.74,1844.56 1731.56,1843.75 1731.56,1835.56 1740.55,1844.56 ; 1740.55,1844.56 2325.55,1844.56 ; 2325.55,1844.56 2334.61,1844.56 ; 2325.55,1844.56 2335.05,1835.06 ; 2334.61,1844.56 2344.55,1844.56 ; 2334.61,1844.56 2335.05,1844.13 2335.05,1835.06 ; 2335.05,1835.06 2344.55,1844.56 ; 2344.55,1844.56 2928.78,1844.56 ; 2928.78,1844.56 2941.17,1844.56 ; 2928.78,1844.56 2939.64,1833.7 ; 2939.64,1833.7 2950.5,1844.56 ; 2939.64,1833.7 2939.64,1843.03 2941.17,1844.56 ; 2941.17,1844.56 2950.5,1844.56 ; 2950.5,1844.56 3535.49,1844.56 ; 3535.49,1844.56 3544.21,1844.56 ; 3535.49,1844.56 3545.39,1834.65 ; 3544.21,1844.56 3555.3,1844.56 ; 3544.21,1844.56 3545.39,1843.38 3545.39,1834.65 ; 3545.39,1834.65 3555.3,1844.56 ; 3555.3,1844.56 4138.64,1844.56 ; 4138.64,1844.56 4150.95,1844.56 ; 4138.64,1844.56 4150.01,1833.19 ; 4150.01,1833.19 4161.38,1844.56 ; 4150.01,1833.19 4150.01,1843.61 4150.95,1844.56 ; 4150.95,1844.56 4161.38,1844.56 ; 4161.38,1844.56 4747.3,1844.56 ; 4747.3,1844.56 4757.12,1844.56 ; 4747.3,1844.56 4757.72,1834.15 ; 4757.12,1844.56 4768.13,1844.56 ; 4757.12,1844.56 4757.72,1843.97 4757.72,1834.15 ; 4757.72,1834.15 4768.13,1844.56 ; 4768.13,1844.56 5351.66,1844.56 ; 5351.66,1844.56 5363.03,1844.56 ; 5351.66,1844.56 5361.23,1834.99 ; 5361.23,1834.99 5370.79,1844.56 ; 5361.23,1834.99 5361.23,1842.75 5363.03,1844.56 ; 5363.03,1844.56 5370.79,1844.56 ; 5370.79,1844.56 5950.93,1844.56 ; 5950.93,1844.56 5959.04,1844.56 ; 5950.93,1844.56 5963.21,1832.28 ; 5959.04,1844.56 5973.56,1844.56 ; 5959.04,1844.56 5963.21,1840.39 5963.21,1832.28 ; 5963.21,1832.28 5973.56,1842.63 5973.56,1844.56 ; 5973.56,1844.56 6558.41,1844.56 ; 6558.41,1844.56 6571.18,1844.56 ; 6558.41,1844.56 6568.85,1834.11 ; 6568.85,1834.11 6579.3,1844.56 ; 6568.85,1834.11 6568.85,1842.24 6571.18,1844.56 ; 6571.18,1844.56 6579.3,1844.56 ; 6579.3,1844.56 7158.67,1844.56 ; 7158.67,1844.56 7172.24,1844.56 ; 7158.67,1844.56 7170.54,1832.68 ; 7170.54,1832.68 7182.42,1844.56 ; 7170.54,1832.68 7170.54,1842.86 7172.24,1844.56 ; 7172.24,1844.56 7182.42,1844.56 ; 7182.42,1844.56 7766.34,1844.56 ; 7766.34,1844.56 7779.41,1844.56 ; 7766.34,1844.56 7778.96,1831.94 ; 7778.96,1831.94 7791.58,1844.56 ; 7778.96,1831.94 7778.96,1844.1 7779.41,1844.56 ; 7779.41,1844.56 7791.58,1844.56 ; 7791.58,1844.56 8702.04,1844.56 8720.81,1825.79 S83.1@8720.81,1785.35
  Bottom Layer w7: U2.42@10934.09,1506.72 10934.09,1431.63 10966.52,1399.2 10966.52,1058.92 10982.4,1043.03
  Bottom Layer w10: v1(8720.81,1739.65) 8720.81,855.56 9272.6,303.77 10939.14,303.77 11003.95,368.58 11003.95,1021.49 10982.4,1043.03
PA4: S25.1 S26.1 S27.1 S28.1 S29.1 S30.1 S64.1 S65.1 S66.1 S67.1 S68.1 S69.1 S84.1 U2.36 | length 13205
  Top Layer w7: 9473.87,1252.82 9482.67,1244.02 ; 9482.67,1252.19 9482.67,1244.02 ; 9492.71,1252.82 9491.47,1252.82 9482.67,1244.02 ; v1(11071.46,1121.21) 10938.1,1121.21 10873.48,1056.58 10762.31,945.42 9551.34,945.42 9482.67,1014.08 9482.67,1244.02
  Top Layer w10: S25.1@1035.51,1178.83 1035.51,1218.07 1070.26,1252.82 1992.05,1252.82 ; S26.1@2003.11,1178.83 2003.11,1241.75 ; S27.1@2608.46,1178.83 2608.46,1243.41 ; S28.1@3214.49,1178.83 3214.49,1242.03 ; S29.1@3819.1,1178.83 3819.1,1238.75 ; S30.1@4423.72,1178.83 4423.72,1243.73 ; S64.1@5028.29,1178.83 5028.29,1238.51 ; S65.1@5634.21,1178.83 5634.21,1241.74 ; S66.1@6240.4,1178.83 6240.4,1241.79 ; S67.1@6841.4,1178.83 6841.4,1242.41 ; S68.1@7445.87,1178.83 7445.87,1241.42 ; S69.1@8449.06,1178.83 8449.06,1238.2 ; 9491.47,1252.82 9473.87,1252.82 8463.01,1252.82 ; 9492.71,1252.82 10495.72,1252.82 10569.71,1178.83 S84.1@10620.02,1178.83 ; 1992.05,1252.82 2002.15,1252.82 ; 1992.05,1252.82 2003.11,1241.75 ; 2002.15,1252.82 2014.18,1252.82 ; 2002.15,1252.82 2003.11,1251.85 2003.11,1241.75 ; 2003.11,1241.75 2014.18,1252.82 ; 2014.18,1252.82 2599.05,1252.82 ; 2599.05,1252.82 2607.51,1252.82 ; 2599.05,1252.82 2608.46,1243.41 ; 2607.51,1252.82 2617.86,1252.82 ; 2607.51,1252.82 2608.46,1251.87 2608.46,1243.41 ; 2608.46,1243.41 2617.86,1252.82 ; 2617.86,1252.82 3203.7,1252.82 ; 3203.7,1252.82 3213.64,1252.82 ; 3203.7,1252.82 3214.49,1242.03 ; 3213.64,1252.82 3225.27,1252.82 ; 3213.64,1252.82 3214.49,1251.97 3214.49,1242.03 ; 3214.49,1242.03 3225.27,1252.82 ; 3225.27,1252.82 3805.04,1252.82 ; 3805.04,1252.82 3817.62,1252.82 ; 3805.04,1252.82 3819.1,1238.75 ; 3817.62,1252.82 3833.16,1252.82 ; 3817.62,1252.82 3819.1,1251.34 3819.1,1238.75 ; 3819.1,1238.75 3833.16,1252.82 ; 3833.16,1252.82 4414.63,1252.82 ; 4414.63,1252.82 4427.41,1252.82 ; 4414.63,1252.82 4423.72,1243.73 ; 4423.72,1243.73 4432.81,1252.82 ; 4423.72,1243.73 4423.72,1249.12 4427.41,1252.82 ; 4427.41,1252.82 4432.81,1252.82 ; 4432.81,1252.82 5015.11,1252.82 ; 5015.11,1252.82 5027.37,1252.82 ; 5015.11,1252.82 5015.11,1251.68 5028.29,1238.51 ; 5027.37,1252.82 5039.33,1252.82 ; 5027.37,1252.82 5028.29,1251.9 5028.29,1241.78 ; 5028.29,1238.51 5028.29,1241.78 ; 5028.29,1241.78 5039.33,1252.82 ; 5039.33,1252.82 5623.13,1252.82 ; 5623.13,1252.82 5634.56,1252.82 ; 5623.13,1252.82 5634.21,1241.74 ; 5634.21,1241.74 5645.28,1252.82 ; 5634.21,1241.74 5634.21,1252.46 5634.56,1252.82 ; 5634.56,1252.82 5645.28,1252.82 ; 5645.28,1252.82 6229.37,1252.82 ; 6229.37,1252.82 6239.97,1252.82 ; 6229.37,1252.82 6240.4,1241.79 ; 6239.97,1252.82 6251.44,1252.82 ; 6239.97,1252.82 6240.4,1252.38 6240.4,1241.79 ; 6240.4,1241.79 6251.44,1252.82 ; 6251.44,1252.82 6830.98,1252.82 ; 6830.98,1252.82 6839.39,1252.82 ; 6830.98,1252.82 6841.4,1242.41 ; 6839.39,1252.82 6851.81,1252.82 ; 6839.39,1252.82 6841.4,1250.81 6841.4,1242.41 ; 6841.4,1242.41 6851.81,1252.82 ; 6851.81,1252.82 7434.48,1252.82 ; 7434.48,1252.82 7442.33,1252.82 ; 7434.48,1252.82 7445.87,1241.42 ; 7442.33,1252.82 7456.38,1252.82 ; 7442.33,1252.82 7445.87,1249.27 7445.87,1241.42 ; 7445.87,1241.42 7456.38,1251.93 7456.38,1252.82 ; 7456.38,1252.82 8434.72,1252.82 ; 8434.72,1252.82 8445.47,1252.82 ; 8434.72,1252.82 8434.72,1252.54 8449.06,1238.2 ; 8445.47,1252.82 8463.01,1252.82 ; 8445.47,1252.82 8449.06,1249.23 8449.06,1238.87 ; 8449.06,1238.2 8449.06,1238.87 ; 8449.06,1238.87 8463.01,1252.82
  Bottom Layer w7: U2.36@11016.77,1506.72 11016.77,1448.31 11033.6,1431.48 11033.6,1159.07 v1(11071.46,1121.21)
PA5: S31.1 S32.1 S33.1 S34.1 S35.1 S71.1 S72.1 S85.1 S86.1 S87.1 S_Fn1.1 U2.37 | length 12401.4
  Top Layer w10: S31.1@748.99,573.38 748.99,620.81 771.12,642.94 1502.84,642.94 ; S32.1@1513.74,573.38 1513.74,631.56 ; S33.1@2271.01,573.38 2271.01,629.75 ; S34.1@4526,573.38 4526.93,574.31 4526.93,634.47 ; S35.1@6778.66,573.38 6778.66,631.31 ; S_Fn1.1@7536.95,573.38 7536.95,631.31 ; S71.1@8335.08,573.38 8335.08,630.33 ; S72.1@9096.51,573.38 9096.51,631.6 ; S85.1@10011.76,573.38 10011.76,631.13 ; S86.1@10617.3,573.38 10617.3,632.12 ; S87.1@11220.65,573.38 11220.65,612.79 11190.5,642.94 10628.07,642.94 ; 1502.84,642.94 1515.17,642.94 ; 1502.84,642.94 1502.84,642.46 1513.74,631.56 ; 1513.74,631.56 1525.12,642.94 ; 1513.74,631.56 1513.74,641.51 1515.17,642.94 ; 1515.17,642.94 1525.12,642.94 ; 1525.12,642.94 2257.82,642.94 ; 2257.82,642.94 2271.59,642.94 ; 2257.82,642.94 2271.01,629.75 ; 2271.01,629.75 2271.01,630.9 ; 2271.01,630.9 2271.01,642.36 2271.59,642.94 ; 2271.01,630.9 2283.05,642.94 ; 2271.59,642.94 2283.05,642.94 ; 2283.05,642.94 4518.46,642.94 ; 4518.46,642.94 4526.93,642.94 ; 4518.46,642.94 4526.93,634.47 ; 4526.93,634.47 4527.57,634.47 4536.04,642.94 ; 4526.93,634.47 4526.93,642.94 ; 4526.93,642.94 4536.04,642.94 ; 4536.04,642.94 6769.94,642.94 ; 6769.94,642.94 6780.28,642.94 ; 6769.94,642.94 6769.94,640.03 6778.66,631.31 ; 6778.66,631.31 6778.66,633.92 ; 6778.66,633.92 6778.66,641.32 6780.28,642.94 ; 6778.66,633.92 6787.68,642.94 ; 6780.28,642.94 6787.68,642.94 ; 6787.68,642.94 7525.32,642.94 ; 7525.32,642.94 7536.61,642.94 ; 7525.32,642.94 7536.95,631.31 ; 7536.61,642.94 7548.59,642.94 ; 7536.61,642.94 7536.95,642.59 7536.95,631.31 ; 7536.95,631.31 7548.59,642.94 ; 7548.59,642.94 8322.47,642.94 ; 8322.47,642.94 8333.97,642.94 ; 8322.47,642.94 8335.08,630.33 ; 8333.97,642.94 8345.72,642.94 ; 8333.97,642.94 8335.08,641.84 8335.08,632.29 ; 8335.08,630.33 8335.08,632.29 ; 8335.08,632.29 8345.72,642.94 ; 8345.72,642.94 9085.57,642.94 ; 9085.57,642.94 9096.5,642.94 ; 9085.57,642.94 9085.57,642.54 9096.51,631.6 ; 9096.51,631.6 9096.51,633.28 ; 9096.51,633.28 9096.51,642.93 ; 9096.51,633.28 9106.17,642.94 ; 9096.5,642.94 9106.17,642.94 ; 9106.17,642.94 9999.95,642.94 ; 9999.95,642.94 10009.33,642.94 ; 9999.95,642.94 10011.76,631.13 ; 10009.33,642.94 10021.23,642.94 ; 10009.33,642.94 10011.76,640.51 10011.76,631.13 ; 10011.76,631.13 10021.23,640.6 10021.23,642.94 ; 10021.23,642.94 10606.47,642.94 ; 10606.47,642.94 10616.71,642.94 ; 10606.47,642.94 10617.3,632.12 ; 10616.71,642.94 10628.07,642.94 ; 10616.71,642.94 10617.3,642.36 10617.3,632.17 ; 10617.3,632.12 10617.3,632.17 ; 10617.3,632.17 10628.07,642.94
  Bottom Layer w7: U2.37@11002.99,1506.72 11002.99,1439.75 11019.41,1423.32 11019.41,1118.66 11102.29,1035.78 11102.29,665.55 v1(11123.89,643.95)
PA6: U2.38
PA7: U2.4
PA9: P8.1 U2.6 | length 424
  Bottom Layer w7: P8.1@10417.55,1612.6 U2.6@10841.57,1612.6
PA10: U2.48 Y2.2 | length 464.9
  Bottom Layer w7: Y2.2@10722.28,1202.87 10722.28,1246.28 10732.39,1256.39 10869.86,1256.39 10884.05,1270.58 10884.05,1354.34 10851.41,1386.97 U2.48@10851.41,1506.72
PA11: U2.47 Y2.1 | length 373
  Bottom Layer w7: Y2.1@10820.71,1202.87 10859.31,1202.87 10899.11,1242.67 10899.11,1362.6 10865.19,1396.52 U2.47@10865.19,1506.72
PA12: U2.46
PA13: C5.2 R121.1 R129.2 U2.45 | length 3641
  Top Layer w25: v1(9574.16,1216.63) 9574.16,1020.62 9615.54,979.24 10742.61,979.24 10810.56,1047.19 v1@10810.56,1125.11
  Bottom Layer w7: U2.45@10892.75,1506.72 10892.75,1473.9 ; v1@10798.34,1095.6 10798.34,1107.79 ; v1@10798.34,1095.6 10800.94,1098.2 v1@10807.93,1098.2 ; v1@10798.34,1095.6 v1(10810.53,1095.6) ; 10798.34,1107.79 10801.98,1111.43 ; 10798.34,1107.79 v1@10801.5,1104.63 ; 10798.34,1107.79 v1@10798.34,1124.29 ; v1@10798.34,1124.29 v1@10801.85,1127.79 ; v1@10798.34,1124.29 10798.34,1131.3 ; v1@10798.34,1124.29 v1@10809.74,1124.29 ; 10798.34,1131.3 v1@10801.85,1127.79 ; 10798.34,1131.3 10805.7,1138.66 v1@10810.9,1138.66 ; v1@10801.5,1104.63 v1@10810.53,1104.63 ; v1@10801.5,1104.63 v1@10807.93,1098.2 ; v1@10801.85,1127.79 10804.19,1125.45 v1@10810.9,1125.45 ; v1@10801.85,1127.79 v1@10810.9,1136.85 ; 10801.98,1111.43 10810.53,1111.43 ; 10801.98,1111.43 10801.98,1116.53 v1@10809.74,1124.29 ; 10801.98,1111.43 10807.69,1117.14 v1@10810.53,1117.14 ; v1@10807.93,1098.2 v1(10810.53,1095.6) ; v1@10807.93,1098.2 v1@10810.53,1098.2 ; v1@10809.74,1124.29 v1@10810.53,1125.08 ; v1(10810.53,1095.6) v1@10818.09,1103.16 ; v1(10810.53,1095.6) v1@10810.53,1098.2 ; v1(10810.53,1095.6) 10817.03,1095.6 10827.6,1106.16 ; v1@10810.53,1098.2 v1@10810.53,1104.63 ; v1@10810.53,1098.2 v1@10816.96,1104.63 ; v1@10810.53,1104.63 v1@10816.96,1104.63 ; v1@10810.53,1104.63 10810.53,1111.06 ; 10810.53,1111.06 10810.53,1111.43 ; 10810.53,1111.06 10810.9,1111.43 ; 10810.53,1111.06 10810.88,1110.71 ; 10810.53,1111.43 10810.9,1111.43 ; 10810.53,1111.43 v1@10810.53,1117.14 ; v1@10810.53,1117.14 v1@10810.53,1125.08 ; v1@10810.53,1117.14 v1@10810.9,1117.14 ; v1@10810.53,1125.08 v1@10810.9,1125.45 ; 10810.88,1110.71 10823.04,1110.71 ; 10810.88,1110.71 v1@10816.96,1104.63 ; 10810.9,1111.43 v1@10810.9,1117.14 ; 10810.9,1111.43 v1@10816.61,1117.14 ; v1@10810.9,1117.14 v1@10816.61,1117.14 ; v1@10810.9,1117.14 v1@10810.9,1125.45 ; v1@10810.9,1125.45 v1@10810.9,1136.85 ; v1@10810.9,1125.45 v1(10811.41,1125.95) ; v1@10810.9,1136.85 v1@10810.9,1138.66 ; v1@10810.9,1136.85 v1@10812.72,1138.66 ; v1@10810.9,1138.66 v1@10812.72,1138.66 ; v1(10811.41,1125.95) 10811.41,1122.35 v1@10816.61,1117.14 ; v1(10811.41,1125.95) v1@10818.42,1118.95 ; v1(10811.41,1125.95) v1@10823.98,1125.95 ; v1(10811.41,1125.95) v1@10818.42,1132.96 ; v1@10812.72,1138.66 v1@10818.42,1132.96 ; v1@10812.72,1138.66 10824.12,1138.66 ; v1@10816.61,1117.14 v1@10816.97,1117.5 ; v1@10816.61,1117.14 10823.04,1110.71 ; v1@10816.96,1104.63 10818.09,1103.5 v1@10818.09,1103.16 ; v1@10816.96,1104.63 10823.04,1110.71 ; v1@10816.97,1117.5 v1@10818.42,1118.95 ; v1@10816.97,1117.5 v1@10819.86,1117.5 ; v1@10818.09,1103.16 10824.35,1109.41 ; v1@10818.42,1118.95 v1@10824.7,1125.23 ; v1@10818.42,1118.95 v1@10819.86,1117.5 ; v1@10818.42,1132.96 10825.42,1125.95 ; v1@10818.42,1132.96 10824.12,1138.66 ; v1@10818.42,1132.96 10832.43,1132.96 ; v1@10819.86,1117.5 10829.83,1117.5 ; 10823.04,1110.71 10829.83,1117.5 ; 10823.04,1110.71 10824.35,1109.41 ; v1@10823.98,1125.95 10825.42,1125.95 ; v1@10823.98,1125.95 v1@10824.7,1125.23 ; 10824.12,1138.66 10842.29,1138.66 ; 10824.35,1109.41 10832.43,1117.5 ; 10824.35,1109.41 10827.6,1106.16 ; v1@10824.7,1125.23 10825.42,1125.95 ; v1@10824.7,1125.23 10831.13,1118.8 ; 10825.42,1125.95 10832.43,1132.96 ; 10825.42,1125.95 10829.58,1125.95 ; 10827.6,1106.16 10847.39,1125.95 ; 10829.58,1125.95 10832.43,1125.95 ; 10829.58,1125.95 10832.43,1128.81 ; 10829.83,1117.5 10831.13,1118.8 ; 10829.83,1117.5 10832.43,1117.5 ; 10831.13,1118.8 10832.43,1120.1 ; 10831.13,1118.8 10832.43,1117.5 ; 10832.43,1117.5 10832.43,1120.1 ; 10832.43,1120.1 10838.29,1125.95 ; 10832.43,1120.1 10832.43,1125.95 ; 10832.43,1125.95 10838.29,1125.95 ; 10832.43,1125.95 10832.43,1128.81 ; 10832.43,1128.81 10833.93,1130.31 ; 10832.43,1128.81 10832.43,1131.81 ; 10832.43,1131.81 10832.43,1132.96 ; 10832.43,1131.81 10833.93,1130.31 ; 10832.43,1132.96 10836.59,1132.96 ; 10833.93,1130.31 10838.29,1125.95 ; 10833.93,1130.31 10836.59,1132.96 ; 10836.59,1132.96 10842.29,1138.66 ; 10836.59,1132.96 10845.29,1132.96 ; 10838.29,1125.95 10847.39,1125.95 ; 10838.29,1125.95 10845.29,1132.96 ; 10842.29,1138.66 10916.5,1212.88 10916.5,1368.84 10887.24,1398.1 10887.24,1406.91 ; 10845.29,1132.96 10921.25,1208.92 10921.25,1372.9 10887.24,1406.91 ; 10847.39,1125.95 10926.2,1204.77 10926.2,1377.22 10892.75,1410.67 10892.75,1473.9 ; 10887.24,1406.91 10887.24,1468.39 10892.75,1473.9
  Bottom Layer w25: v1@9574.22,1184.26 C5.2@9574.22,1311.74 R129.2@9574.22,1380.06 9574.22,1457.51 R121.1@9574.94,1458.22
  other v1: 9573.64,1184.88
PA14: R117.1 U1.1 U2.44 | length 1916
  Top Layer w7: v1(10209.21,1221.25) 10209.21,1044.66 10208.59,1044.04 10244.25,1008.38 10706.96,1008.38 v1(10755.97,1057.39)
  Bottom Layer w7: v1(10755.97,1057.39) 10827.03,1057.39 10940.52,1170.88 10940.52,1383.15 10906.53,1417.14 U2.44@10906.53,1506.72
  Bottom Layer w10: U1.1@9904.01,1530.18 9996.38,1530.18 R117.1@9997.61,1528.94 10142.95,1528.94 10209.21,1462.69 v1(10209.21,1221.25)
PA15: R120.1 R128.2 U2.43 | length 7007.1
  Bottom Layer w7: U2.43@10920.31,1506.72 10920.31,1424.55 10953.52,1391.34 10953.52,1039.02 10964.71,1027.83
  Bottom Layer w10: R120.1@9515.84,3972.2 9515.84,3901.51 R128.2@9513.18,3898.85 9513.18,3862.14 9290.15,3639.12 9290.15,2286.86 8771.2,1767.9 8771.2,856.5 9289.67,338.02 10925.58,338.02 10977.39,389.83 10977.39,1015.16 10964.71,1027.83
PB0: U2.24
PB1: U2.23
PB2: U2.22
PB3: U2.21
PB12: P7.3 U2.14 | length 3110.2
  Top Layer w7: v1(10849.85,1858.12) 10849.85,1878.28 11323.46,2351.9 11323.46,3842.16 10887.53,4278.09 P7.3@10887.53,4419.13
  Bottom Layer w7: v1@10851.88,1860.15 10892.75,1819.28 U2.14@10892.75,1704.68
PB13: P7.2 U2.13 | length 3241.8
  Top Layer w7: 10787.53,4378.88 10787.53,4352.28 ; P7.2@10787.53,4419.13 10787.53,4352.28 ; v1(10810.04,1906.43) 10859.54,1906.43 11300.73,2347.61 ; 11285.34,2332.16 11307.42,2354.24 11307.42,3832.38 11300.73,3839.08 10787.53,4352.28
  Bottom Layer w7: v1(10810.04,1906.43) 10810.04,1847.17 10878.97,1778.24 U2.13@10878.97,1704.68
UD+: P6.2 P9.A6 P9.B6 S70.3 U2.15 | length 5351.3
  Top Layer w7: v1(9409.53,4255.05) 9434.16,4230.42 9467.9,4230.42 v1(9485.92,4248.44) ; v1@9996.11,4275.54 P6.2@9996.11,4420.24
  Bottom Layer w7: P9.A6@9411.38,4172.15 9411.38,4275.03 9434.5,4298.14 9662.75,4298.14 9685.36,4275.54 v1(9995.02,4275.54) ; P9.B6@9450.75,4172.15 9450.75,4213.75 9509.14,4272.14 9644.47,4272.14 9699.32,4217.3 9699.32,3938.07 9441.39,3680.14 9441.39,3646.67 9441.39,2116.51 9489.51,2068.39 10703.62,2068.39 10906.92,1865.1 10906.92,1838.5 U2.15@10906.53,1704.68 ; P6.2@9994.74,4418.02 S70.3@10127.09,4418.02
UD-: P9.A7 P9.B7 U2.16 | length 4535
  Top Layer w7: v1(9367.93,4243.38) 9367.93,4261.58 9387.23,4280.87 9427.68,4280.87 v1(9447.45,4261.1)
  Bottom Layer w7: v1@9364.82,4246.94 9391.7,4220.06 P9.B7@9391.7,4172.15 ; P9.A7@9431.07,4172.15 9431.07,4243.35 9472.86,4285.14 9649.86,4285.14 9715.7,4219.3 9715.7,3962.16 9715.7,3932.9 9635.84,3853.03 9460.14,3677.34 9460.14,2120.26 9495.48,2084.93 10706.66,2084.93 10920.31,1871.28 U2.16@10920.31,1704.68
